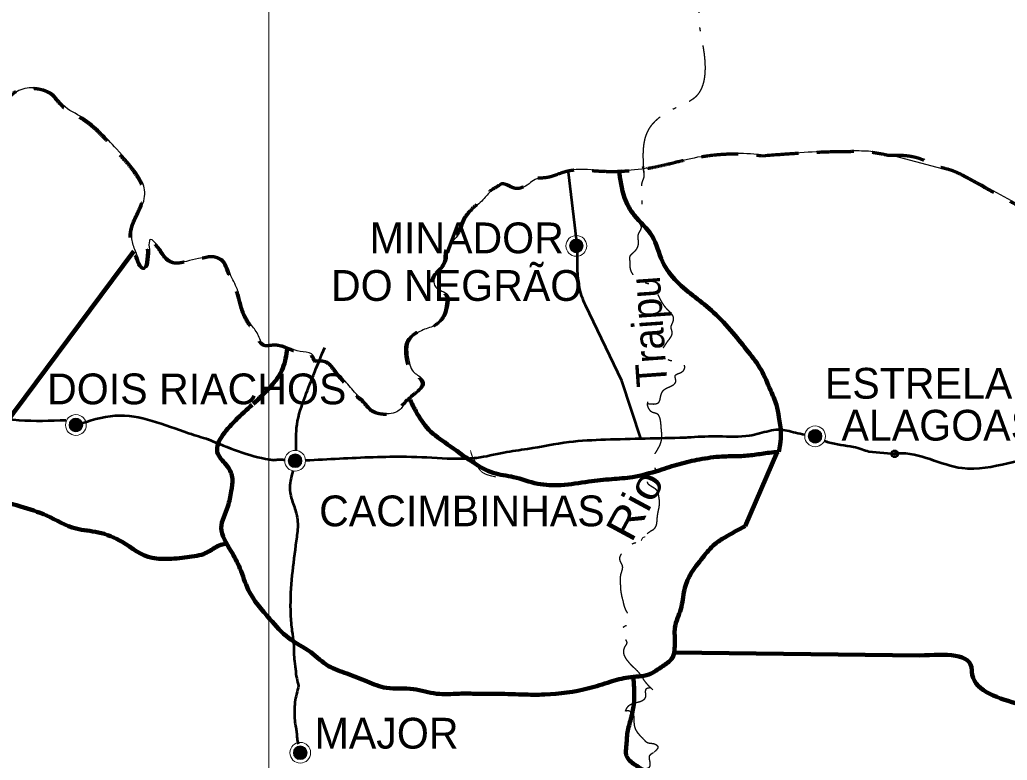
# Model space of a CAD drawing. Extents: x 512883 to 1063249, y 8784064 to 9081064.
# Drawn here: x 707317 to 755485, y 8945263 to 8981350 of the extents above; entities that cross this region are included whole.
import ezdxf

# ---------------------------------------------------------------- set-up
doc = ezdxf.new("R2010")
doc.units = 0
doc.header["$LTSCALE"] = 600
doc.header["$PDMODE"] = 32
doc.header["$PDSIZE"] = 300
doc.linetypes.add('DOT_DASHED', pattern=[7.7, 5, -1.2, 0.3, -1.2])
doc.linetypes.add('MEDIUM_DASHED', pattern=[4.5, 3, -1.5])
for name, color, linetype, lineweight in [('1', 7, 'Continuous', 25), ('10', 7, 'Continuous', 53), ('13', 7, 'Continuous', 90), ('20', 7, 'Continuous', 53), ('4', 7, 'Continuous', 13), ('5', 7, 'Continuous', 13), ('7', 7, 'Continuous', 13)]:
    doc.layers.add(name, color=color, linetype=linetype, lineweight=lineweight)

msp = doc.modelspace()

# ---------------------------------------------------------------- linework, layer by layer
at = {"layer": '1', "lineweight": 13}
msp.add_line((719468, 8831691.5), (719468, 9039622), dxfattribs=at)
at = {"layer": '10'}
for p, q in [((734465.8, 8970661.9), (734079.7, 8973916.1)), ((736689.1, 8963752.3), (734911.5, 8967437.8)), ((737616.8, 8960937.3), (736689.1, 8963752.3)), ((748733, 8960303.9), (750009.2, 8960196.7))]:
    msp.add_line(p, q, dxfattribs=at)
for points in [[(734911.5, 8967437.8), (734735.5, 8967867), (734521.7, 8969592.1), (734526.8, 8969856.2), (734531.9, 8970037.6)], [(710095.1, 8961612.2), (711975.7, 8962060.5), (715550.1, 8961209.8), (716524.6, 8960901)], [(739750.2, 8960990), (740069.8, 8961013.6), (741413.6, 8961055), (742910, 8961091.3), (743877.1, 8961319.2), (744319.9, 8961381.4), (745159.8, 8961231.2), (745615.5, 8961134.3)], [(716504.4, 8960907.4), (719500.2, 8959922.9), (719710, 8959891.7)], [(728165.2, 8959972.1), (728754.8, 8959967.2), (729599.7, 8960008.6), (730928.2, 8960262.5), (732088.7, 8960443.8), (734109.4, 8960775.3), (735885.8, 8960894.5), (739750.2, 8960990)], [(746576.9, 8960831.1), (746747.9, 8960770.1), (747984.7, 8960537), (748391.9, 8960423.1), (748733, 8960303.9)], [(720248.7, 8959891.2), (720043.6, 8959901.7), (719817.2, 8959894.6), (719710, 8959891.7)], [(721260.6, 8959880.5), (724555.5, 8960039.7), (726184.3, 8960060.4), (728165.2, 8959972.1)], [(760025.4, 8958989.5), (758791.9, 8960070.6), (757224, 8960086.4), (755519.6, 8959726.1), (753291.3, 8959489.3), (750147.9, 8960209.6), (749997.5, 8960195.6)], [(720637.5, 8959358.1), (720493.7, 8958423.5), (720600.6, 8957921), (720809.3, 8957273.5), (720870.4, 8956512), (720773.7, 8955745.3), (720763.1, 8955633.6)], [(720771.7, 8955725), (720524.3, 8952373), (720595.5, 8951564.9), (720671.9, 8950969.1), (720702.4, 8950212.8), (720763.5, 8949710.3), (720824.6, 8949254.5), (720916.2, 8948886.7)], [(720916.2, 8948886.7), (720742.3, 8948088.2), (720732, 8947211.2), (720783.5, 8946853.1), (720819.6, 8946619.6), (720845.4, 8946323.8), (720896.9, 8946048.7)]]:
    msp.add_spline(points, degree=3, dxfattribs=at)
msp.add_point((749997.5, 8960195.6), dxfattribs=at)
at = {"layer": '13', "lineweight": 25}
for p, q in [((753350.1, 8973817.3), (749745.8, 8974773.5)), ((732684.5, 8973664.1), (732612.3, 8973629.6)), ((721878.7, 8964741.6), (721780.9, 8964695.6))]:
    msp.add_line(p, q, dxfattribs=at)
at = {"layer": '13'}
for p, q in [((712886.7, 8970072.6), (705949.8, 8960800.5)), ((742703.1, 8956675), (744263.7, 8960282.7)), ((739246.1, 8950519.4), (751215.9, 8950362.8))]:
    msp.add_line(p, q, dxfattribs=at)
at = {"layer": '13', "linetype": 'MEDIUM_DASHED', "lineweight": 70}
msp.add_lwpolyline([(721689.3, 8964678.9), (721746.9, 8964737.1), (721787.2, 8964724.9)], dxfattribs=at)
for points in [[(706159.5, 8976374.6), (706429.7, 8976990.8), (706677.5, 8977367.7), (706839.2, 8977612.2), (707097.1, 8977836.4), (707895.8, 8978014.7), (708826.1, 8977734.5), (709336.7, 8977179.2), (710297.3, 8976562.9), (711940.3, 8975044.9), (713017.2, 8973740.8), (713315.5, 8973043), (713300.3, 8972620.2), (712921.1, 8971662.5), (712744.2, 8971209.2), (712703.7, 8970582.6), (712895.8, 8969991.7), (713057.6, 8969558.7), (713234.6, 8969283.7), (713361, 8969242.9), (713527.8, 8969645.3), (713553.1, 8970159.8), (713553.1, 8970567.3), (713573.3, 8970608.1), (713816, 8970480.7), (714169.9, 8970047.8), (714382.2, 8969752.3), (714801.8, 8969518), (715363, 8969558.7), (715944.4, 8969696.3), (716348.8, 8969767.6), (716596.6, 8969818.5), (717142.6, 8969630.1), (717486.3, 8968957.7), (717840.2, 8968188.5), (718017.2, 8967602.7), (718194.1, 8967037.2), (718527.8, 8966451.5), (718871.6, 8965931.9), (719008.1, 8965636.4), (719164.8, 8965514.2), (719738.5, 8965507.8), (720910.6, 8965166.7), (721451.4, 8965051.3), (721689.3, 8964678.9)], [(732593, 8973647.4), (733055.8, 8973679.3), (734017.8, 8973979.7), (735473.6, 8973984.9), (738247.6, 8974166.2), (740120.7, 8974596.2), (742869.3, 8974793), (743500, 8974726.3)], [(743500, 8974726.3), (746671.5, 8974917.3), (747832, 8974938.1), (748738.1, 8974912.2), (749654.2, 8974756.8)], [(749654.2, 8974756.8), (751133.8, 8974617.1), (752173.2, 8974188.4), (752784.7, 8974014.9), (753246, 8973806.2)], [(753258.6, 8973800.6), (756145, 8972228.3), (758126.6, 8971149.5), (759060.8, 8970276.1), (759489.1, 8967898.4), (760156.5, 8967525), (761008.9, 8966776.5), (761311.1, 8966714.8), (761418.5, 8967904.7), (761819.8, 8967968.6), (761964.4, 8967614.3), (763228, 8966032.4), (763365, 8966366.7), (763825, 8966576.9), (764463.7, 8966975.4), (765249.4, 8966811), (765751.8, 8966812.7), (766047.5, 8967335.3), (766506.4, 8968208.9)], [(721787.2, 8964724.9), (722154.8, 8964707.5), (722726.1, 8964148.7), (723165.9, 8963646.2), (723691.6, 8963046.4), (724060.7, 8962718.2), (724460, 8962302.9), (724869.5, 8962159.4), (725238.6, 8962133.7), (725617.7, 8962226), (726001.9, 8962600.3), (726527.7, 8963087.4), (726891.6, 8963425.8), (726957.3, 8963579.6), (726856.2, 8963835.9), (726416.4, 8964189.7), (726254.7, 8964517.8), (726148.5, 8965138.2), (726214.2, 8965650.9), (726461.9, 8965958.6), (727053.4, 8966276.4), (727660, 8966527.7), (728034.1, 8966999.4), (728155.5, 8967542.8), (728145.3, 8967871), (727907.7, 8968070.9), (727569, 8968255.5), (727432.5, 8968465.7), (727493.2, 8968829.7), (727852.1, 8969245), (728059.4, 8969639.8), (728079.6, 8969952.6), (728180.7, 8970301.2), (728615.5, 8970865.2), (728797.5, 8971203.6), (728984.5, 8971654.8), (729358.6, 8972116.2), (729884.4, 8972628.9), (730283.7, 8973034), (730678, 8973274.9), (730804.4, 8973357), (731244.2, 8973223.7), (731704.3, 8973151.9), (732068.2, 8973336.5), (732361.5, 8973551.8), (732520.8, 8973612.9)]]:
    msp.add_spline(points, degree=3, dxfattribs=at)
at = {"layer": '13', "lineweight": 25}
for points in [[(721780.9, 8964695.6), (721542.9, 8965068), (721002.1, 8965183.4), (719830.1, 8965524.5), (719256.3, 8965530.9), (719099.6, 8965653.1), (718963.1, 8965948.6), (718619.3, 8966468.2), (718285.7, 8967054), (718108.7, 8967619.4), (717931.8, 8968205.2), (717577.9, 8968974.4), (717234.1, 8969646.8), (716688.1, 8969835.2), (716440.4, 8969784.3), (716035.9, 8969713), (715454.5, 8969575.5), (714893.4, 8969534.7), (714473.7, 8969769), (714261.4, 8970064.5), (713907.5, 8970497.5), (713664.8, 8970624.8), (713644.6, 8970584.1), (713644.6, 8970176.5), (713619.3, 8969662.1), (713452.5, 8969259.6), (713326.1, 8969300.4), (713149.2, 8969575.5), (712987.4, 8970008.4), (712795.3, 8970599.3), (712835.7, 8971225.9), (713012.7, 8971679.2), (713391.8, 8972636.9), (713407, 8973059.7), (713108.7, 8973757.6), (712031.9, 8975061.6), (710388.8, 8976579.6), (709428.2, 8977196), (708917.6, 8977751.2), (707987.4, 8978031.4), (707188.6, 8977853.1), (706930.8, 8977628.9), (706769, 8977384.4), (706521.3, 8977007.5), (706251, 8976391.3)], [(743591.5, 8974743), (742960.8, 8974809.7), (740212.2, 8974612.9), (738339.1, 8974182.9), (735565.1, 8974001.6), (734109.3, 8973996.4), (733147.3, 8973696), (732684.5, 8973664.1)], [(749745.8, 8974773.5), (748829.6, 8974928.9), (747923.6, 8974954.8), (746763.1, 8974934), (743591.5, 8974743)], [(766531.3, 8968098.7), (766139.1, 8967352), (765843.4, 8966829.4), (765340.9, 8966827.7), (764555.2, 8966992.2), (763916.5, 8966593.6), (763456.6, 8966383.4), (763319.6, 8966049.1), (762055.9, 8967631), (761911.3, 8967985.3), (761510.1, 8967921.4), (761402.6, 8966731.5), (761100.5, 8966793.2), (760248, 8967541.7), (759580.7, 8967915.2), (759152.4, 8970292.8), (758218.2, 8971166.2), (756236.6, 8972245), (753350.1, 8973817.3)], [(732612.3, 8973629.6), (732453, 8973568.5), (732159.8, 8973353.2), (731795.8, 8973168.6), (731335.8, 8973240.4), (730896, 8973373.7), (730769.6, 8973291.7), (730375.3, 8973050.7), (729975.9, 8972645.6), (729450.2, 8972132.9), (729076.1, 8971671.5), (728889, 8971220.3), (728707, 8970881.9), (728272.3, 8970317.9), (728171.2, 8969969.3), (728150.9, 8969656.5), (727943.7, 8969261.7), (727584.8, 8968846.5), (727524.1, 8968482.4), (727660.6, 8968272.2), (727999.3, 8968087.6), (728236.9, 8967887.7), (728247, 8967559.5), (728125.7, 8967016.1), (727751.6, 8966544.4), (727144.9, 8966293.2), (726553.5, 8965975.3), (726305.8, 8965667.6), (726240, 8965154.9), (726346.2, 8964534.6), (726508, 8964206.4), (726947.8, 8963852.6), (727048.9, 8963596.3), (726983.2, 8963442.5), (726619.2, 8963104.1), (726093.4, 8962617), (725709.2, 8962242.7), (725330.1, 8962150.4), (724961.1, 8962176.1), (724551.6, 8962319.6), (724152.2, 8962734.9), (723783.2, 8963063.1), (723257.4, 8963662.9), (722817.6, 8964165.4), (722246.4, 8964724.2), (721878.7, 8964741.6)]]:
    msp.add_spline(points, degree=3, dxfattribs=at)
at = {"layer": '13'}
for points in [[(736550.5, 8974034.8), (736820.9, 8972666.4), (737287.4, 8971829), (738159.6, 8970807.9), (738666.7, 8969562.1), (739376.6, 8968581.7), (741161.5, 8967090.8), (742094.6, 8966090.1), (742865.3, 8965150.7), (743473.8, 8964292.9), (743940.3, 8963292.1), (744224.3, 8962577.3), (744346, 8961985.1), (744447.4, 8961209), (744406.9, 8960657.6), (744346, 8960289.9)], [(720360, 8965327.6), (720148.1, 8964374.6), (719559.9, 8963476), (718702.8, 8962631.9)], [(726317.6, 8962899.8), (726638.7, 8962271), (727267.5, 8961372.4), (728180.3, 8960657.6), (729397.3, 8959799.8), (730411.4, 8959268.8), (731405.3, 8959064.6), (732581.7, 8958737.8), (733717.6, 8958676.5), (735076.6, 8958839.9), (736192.2, 8958962.4), (737206.3, 8959064.6), (738504.4, 8959391.3), (739498.3, 8959697.7), (740471.9, 8959922.3), (741567.2, 8960065.3), (742439.4, 8960085.7), (743149.3, 8960147), (743879.5, 8960249.1), (744346, 8960289.9)], [(718651.7, 8962582.6), (717835.8, 8961821.7), (716983.9, 8960187.8), (717450.4, 8959575.1), (717693.8, 8958982.8), (717633, 8958370.2), (717470.7, 8957634.9), (717146.2, 8956593.3), (717612.7, 8955470.1), (718058.9, 8954612.3), (718464.6, 8953570.7), (719519.3, 8952141.1), (720432.1, 8951222.1), (721507.1, 8950527.7), (722379.3, 8949853.7), (723271.7, 8949486.1), (724265.6, 8949098), (725198.6, 8948791.7), (726517, 8948730.4), (727652.9, 8948505.8), (728748.2, 8948505.8), (729519, 8948505.8), (730452, 8948505.8), (731831.2, 8948464.9), (732926.6, 8948464.9), (735076.6, 8948771.3), (736111, 8949077.6), (737003.5, 8949302.3), (737997.4, 8949445.2), (738687, 8949853.7), (739112.9, 8950200.9), (739275.2, 8950588.9)], [(703678.1, 8958901.2), (704347.5, 8958513.1), (705807.8, 8958043.4), (707349.4, 8957634.9), (708627.2, 8957185.6), (710067.3, 8956552.5), (711142.3, 8956368.7), (712318.8, 8955899), (713779.2, 8955122.9), (714205.1, 8955082), (715239.6, 8955122.9), (716187.9, 8955271)], [(739237.1, 8950497.7), (739275.2, 8950936.1), (739275.2, 8951732.6), (739559.2, 8952631.2), (739741.7, 8953570.7), (740025.7, 8954306), (740634.2, 8955143.3), (741222.4, 8955796.8), (741709.2, 8956123.6), (742703.1, 8956675)], [(716187.9, 8955271), (716524, 8955430.5), (717125.9, 8955756), (717430.1, 8955819.6)], [(751215.9, 8950362.8), (753762, 8949641), (753762.7, 8949578.4), (755890.1, 8948041), (757527.9, 8947149), (757853, 8946837), (757993.7, 8946837.5), (759997, 8947428.2), (761876.7, 8948289.9), (763609.1, 8949756.3), (764914.3, 8949864.8), (765859.8, 8949784.4), (767129, 8949517.2), (767844.7, 8948413.5), (770470.8, 8945520.4)], [(737243.3, 8949342.3), (737287.4, 8948648.7), (737267.2, 8947974.8), (737125.2, 8947280.4), (736962.9, 8946626.8), (736902.1, 8945932.4), (736902.1, 8945524), (737246.9, 8945095.1), (737875.7, 8944645.8), (738058.2, 8944359.9)]]:
    msp.add_spline(points, degree=3, dxfattribs=at)
at = {"layer": '20'}
for points in [[(720798.7, 8960361.7), (720842.3, 8961626.5), (721234.4, 8962978.6), (722193, 8965377.4)], [(709566.7, 8961827.1), (707282.2, 8961827.1), (704947, 8962237.3), (703424, 8962724.3), (701647.2, 8963211.3), (700048.1, 8962673), (698753.5, 8961673.3), (697357.5, 8961827.1), (696189.8, 8962468), (695352.2, 8963493.3), (694574.4, 8963871.8), (693066.1, 8963771.4)]]:
    msp.add_spline(points, degree=3, dxfattribs=at)
at = {"layer": '4', "linetype": 'DOT_DASHED', "lineweight": 25}
for points in [[(737771.9, 8973878.1), (738007.4, 8976016.7), (739042.5, 8976929.5), (740383.3, 8977697.2), (740702.9, 8979750.7), (740453.3, 8981596.7), (740956.7, 8983442.9), (741968, 8985558.7), (742250.1, 8986512.9), (742185.8, 8987633), (742689.7, 8989292.4), (743519, 8990993.4)], [(737946.5, 8962644.2), (738502.1, 8962723.1), (738588.6, 8963033.9), (738731.1, 8963303.3), (739097.6, 8963500.1), (739316.5, 8963722.9), (739291, 8964002.6), (739591.3, 8964173.5), (739749.1, 8964370.4), (739642.2, 8964665.7), (739464.1, 8964727.8), (739087.4, 8964727.8), (738878.8, 8964815.9), (738649.7, 8965142.2), (738782, 8965468.6), (738960.2, 8965727.6), (739143.4, 8966121.3), (739087.4, 8966370), (739153.6, 8966556.4), (739209.6, 8966820.6), (738899.1, 8967235.1), (738593.7, 8967675.4), (738344.3, 8968162.3), (738217.1, 8968359.2), (737967.6, 8968483.5), (737484.1, 8968680.3), (737285.6, 8968866.8), (737112.5, 8969188), (737087.1, 8969576.5), (737087.1, 8969814.8), (737336.5, 8970089.4), (737499.4, 8970462.3), (737499.4, 8970907.8), (737641.9, 8971239.4), (737484.1, 8971591.6), (737509.5, 8971778.1), (737667.3, 8972249.5), (737667.3, 8972570.7), (737611.3, 8972891.9), (737626.6, 8972995.5), (737687.7, 8973446.2), (737779.3, 8973746.6), (737753.9, 8973974.5), (737708.1, 8974155.8), (737692.8, 8974186.9)], [(738201.8, 8948689.8), (737830.2, 8949083.5), (737535, 8949513.5), (737250, 8949798.4), (737005.6, 8950062.6), (736837.7, 8950316.4), (736776.6, 8950518.5), (736847.8, 8950803.4), (736939.5, 8951000.2), (736837.7, 8951176.3), (736685, 8951378.4), (736679.9, 8951632.2), (736817.3, 8951792.8), (737051.5, 8951927.5), (737076.9, 8952207.2), (736903.8, 8952538.7), (736751.1, 8953010.1), (736649.3, 8953491.9), (736623.9, 8953968.5), (736639.2, 8954305.2), (736720.6, 8954724.8), (736608.6, 8954978.6), (736588.3, 8955113.3), (736766.4, 8955439.7), (736970, 8955672.8), (737367, 8955869.6), (737575.7, 8955931.8), (737708.1, 8956040.6), (738003.3, 8956372.1), (738303.6, 8956584.5), (738400.3, 8956879.8), (738415.6, 8957092.2), (738456.3, 8957361.5), (738522.5, 8957744.9), (738491.9, 8958123), (738415.6, 8958382), (738059.3, 8958651.4), (737947.3, 8958786.1), (738013.5, 8958967.4), (738278.1, 8959102.1), (738334.1, 8959412.9), (738196.7, 8959832.5), (738354.5, 8960283.2), (738558.1, 8960656.2), (738634.4, 8960982.5), (738609, 8961443.6), (738563.2, 8961858), (738430.8, 8962127.3), (738130.5, 8962241.3), (738023.6, 8962370.8), (737942.2, 8962578), (737956, 8962722.8)], [(736860.6, 8947657.4), (737015.5, 8947911.8), (737309.3, 8948057.1), (737613.4, 8948140.1), (737840.2, 8948316.6), (737845.4, 8948586.4), (737881.4, 8948742.1), (738092.3, 8948805.9)], [(736860.6, 8947657.4), (736943.3, 8947683.4), (737226.8, 8947512.2), (737273.2, 8947216.4), (737340.2, 8946796), (737613.4, 8946422.4), (737778.3, 8946251.1), (737891.8, 8946147.3), (738097.9, 8946090.2), (738278.3, 8946059.1), (738438.1, 8945934.5), (738255.1, 8945651.8)], [(737337.2, 8944270.8), (737386.6, 8944419.2), (737536.1, 8944445.1), (737618.6, 8944434.7), (737665, 8944766.9), (737788.7, 8944849.9), (737938.1, 8944875.8), (738030.9, 8944932.9), (738051.6, 8945233.9), (738041.2, 8945472.7), (738175.3, 8945607.6), (738230.5, 8945639.6)]]:
    msp.add_spline(points, degree=3, dxfattribs=at)
at = {"layer": '4', "linetype": 'DOT_DASHED'}
for points in [[(730546.5, 8959071), (729772.8, 8959392.2), (729533.5, 8959817), (729401.2, 8960050.1), (729304.5, 8960355.7)], [(737632.9, 8955970.8), (737753.9, 8956133.8), (737818.1, 8956144.6)]]:
    msp.add_spline(points, degree=3, dxfattribs=at)
at = {"layer": '5'}
for p, q in [((734148.3, 8970428), (734783.1, 8970428)), ((734159.1, 8970458), (734772.3, 8970458.3)), ((734173.5, 8970488), (734758.2, 8970488)), ((734191.8, 8970518), (734739.9, 8970518)), ((734215.8, 8970548), (734716.2, 8970548)), ((734244.9, 8970578), (734686.5, 8970578)), ((734284.5, 8970608), (734646.9, 8970608)), ((734341.8, 8970638), (734589.6, 8970638)), ((734133.3, 8970338), (734798.1, 8970338)), ((734133.9, 8970308), (734797.8, 8970308)), ((734135.4, 8970368), (734796, 8970368)), ((734136.9, 8970278), (734794.5, 8970278)), ((734140.2, 8970398), (734791.2, 8970398)), ((734142.9, 8970248), (734788.5, 8970248)), ((734151.9, 8970218), (734779.5, 8970218)), ((734164.5, 8970188), (734767.2, 8970188.3)), ((734180.4, 8970158), (734751, 8970158)), ((734201.1, 8970128), (734730.6, 8970128.3)), ((734226.3, 8970097.7), (734705.4, 8970098)), ((734259.6, 8970068), (734671.8, 8970068)), ((734304.6, 8970038), (734626.8, 8970038)), ((734378.4, 8970008), (734552.7, 8970008)), ((709763.8, 8961759.8), (710348.5, 8961759.8)), ((709782.1, 8961789.8), (710330.2, 8961789.8)), ((709806.1, 8961819.8), (710306.5, 8961819.8)), ((709835.2, 8961849.8), (710276.8, 8961849.8)), ((709874.8, 8961879.8), (710237.2, 8961879.8)), ((709932.1, 8961909.8), (710179.9, 8961909.8)), ((709723.6, 8961609.8), (710388.4, 8961609.8)), ((709724.2, 8961579.8), (710388.1, 8961579.8)), ((709725.7, 8961639.8), (710386.3, 8961639.8)), ((709727.2, 8961549.8), (710384.8, 8961549.8)), ((709730.5, 8961669.8), (710381.5, 8961669.8)), ((709733.2, 8961519.8), (710378.8, 8961519.8)), ((709738.6, 8961699.8), (710373.4, 8961699.8)), ((709742.2, 8961489.8), (710369.8, 8961489.8)), ((709749.4, 8961729.8), (710362.6, 8961730.1)), ((709754.8, 8961459.8), (710357.5, 8961460.1)), ((709770.7, 8961429.8), (710341.3, 8961429.8)), ((709791.4, 8961399.8), (710320.9, 8961400.1)), ((709816.6, 8961369.5), (710295.7, 8961369.8)), ((709849.9, 8961339.8), (710262.1, 8961339.8)), ((709894.9, 8961309.8), (710217.1, 8961309.8)), ((709968.7, 8961279.8), (710143, 8961279.8)), ((745861.6, 8961269.1), (746362, 8961269.1)), ((745890.7, 8961299.1), (746332.3, 8961299.1)), ((745930.3, 8961329.1), (746292.7, 8961329.1)), ((745987.6, 8961359.1), (746235.4, 8961359.1)), ((745779.1, 8961059.1), (746443.9, 8961059.1)), ((745779.7, 8961029.1), (746443.6, 8961029.1)), ((745781.2, 8961089.1), (746441.8, 8961089.1)), ((745782.7, 8960999.1), (746440.3, 8960999.1)), ((745786, 8961119.1), (746437, 8961119.1)), ((745788.7, 8960969.1), (746434.3, 8960969.1)), ((745794.1, 8961149.1), (746428.9, 8961149.1)), ((745797.7, 8960939.1), (746425.3, 8960939.1)), ((745804.9, 8961179.1), (746418.1, 8961179.4)), ((745810.3, 8960909.1), (746413, 8960909.4)), ((745819.3, 8961209.1), (746404, 8961209.1)), ((745826.2, 8960879.1), (746396.8, 8960879.1)), ((745837.6, 8961239.1), (746385.7, 8961239.1)), ((745846.9, 8960849.1), (746376.4, 8960849.4)), ((745872.1, 8960818.8), (746351.2, 8960819.1)), ((745905.4, 8960789.1), (746317.6, 8960789.1)), ((745950.4, 8960759.1), (746272.6, 8960759.1)), ((746024.2, 8960729.1), (746198.5, 8960729.1)), ((720415.8, 8959868.8), (721080.6, 8959868.8)), ((720416.4, 8959838.8), (721080.3, 8959838.8)), ((720417.9, 8959898.8), (721078.5, 8959898.8)), ((720422.7, 8959928.8), (721073.7, 8959928.8)), ((720430.8, 8959958.8), (721065.6, 8959958.8)), ((720441.6, 8959988.8), (721054.8, 8959989.1)), ((720456, 8960018.8), (721040.7, 8960018.8)), ((720474.3, 8960048.8), (721022.4, 8960048.8)), ((720498.3, 8960078.8), (720998.7, 8960078.8)), ((720527.4, 8960108.8), (720969, 8960108.8)), ((720567, 8960138.8), (720929.4, 8960138.8)), ((720624.3, 8960168.8), (720872.1, 8960168.8)), ((720419.4, 8959808.8), (721077, 8959808.8)), ((720425.4, 8959778.8), (721071, 8959778.8)), ((720434.4, 8959748.8), (721062, 8959748.8)), ((720447, 8959718.8), (721049.7, 8959719.1)), ((720462.9, 8959688.8), (721033.5, 8959688.8)), ((720483.6, 8959658.8), (721013.1, 8959659.1)), ((720508.8, 8959628.5), (720987.9, 8959628.8)), ((720542.1, 8959598.8), (720954.3, 8959598.8)), ((720587.1, 8959568.8), (720909.3, 8959568.8)), ((720660.9, 8959538.8), (720835.2, 8959538.8)), ((720779.2, 8945876.9), (721220.8, 8945876.9)), ((720818.8, 8945906.9), (721181.2, 8945906.9)), ((720876.1, 8945936.9), (721123.9, 8945936.9)), ((720667.6, 8945636.9), (721332.4, 8945636.9)), ((720668.2, 8945606.9), (721332.1, 8945606.9)), ((720669.7, 8945666.9), (721330.3, 8945666.9)), ((720671.2, 8945576.9), (721328.8, 8945576.9)), ((720674.5, 8945696.9), (721325.5, 8945696.9)), ((720677.2, 8945546.9), (721322.8, 8945546.9)), ((720682.6, 8945726.9), (721317.4, 8945726.9)), ((720686.2, 8945516.9), (721313.8, 8945516.9)), ((720693.4, 8945756.9), (721306.6, 8945757.2)), ((720698.8, 8945486.9), (721301.5, 8945487.2)), ((720707.8, 8945786.9), (721292.5, 8945786.9)), ((720714.7, 8945456.9), (721285.3, 8945456.9)), ((720726.1, 8945816.9), (721274.2, 8945816.9)), ((720735.4, 8945426.9), (721264.9, 8945427.2)), ((720750.1, 8945846.9), (721250.5, 8945846.9)), ((720760.6, 8945396.7), (721239.7, 8945396.9)), ((720793.9, 8945366.9), (721206.1, 8945366.9)), ((720838.9, 8945336.9), (721161.1, 8945336.9)), ((720912.7, 8945306.9), (721087, 8945306.9))]:
    msp.add_line(p, q, dxfattribs=at)
for centre, radius in [((734465.8, 8970329), 506.1), ((734465.8, 8970329), 332.9), ((710056.1, 8961600.8), 506.1), ((710056.1, 8961600.8), 332.9), ((746111.5, 8961050.1), 506.1), ((746111.5, 8961050.1), 332.9), ((720748.3, 8959859.8), 506.1), ((720748.3, 8959859.8), 332.9), ((721000.1, 8945627.9), 506.1), ((721000.1, 8945627.9), 332.9)]:
    msp.add_circle(centre, radius, dxfattribs=at)

# ---------------------------------------------------------------- texts
for s, p in [('MINADOR', (724385.3, 8969970.9)), ('DO NEGRÃO', (722496.9, 8967650.9)), ('ESTRELA DE', (746590.3, 8962884.2)), ('DOIS RIACHOS', (708649.7, 8962610.5)), ('ALAGOAS', (747400.9, 8960840.2)), ('CACIMBINHAS', (721919.6, 8956665)), ('MAJOR', (721699.9, 8945830.3))]:
    msp.add_text(s, height=1500, dxfattribs=at).set_placement(p)
at = {"layer": '7'}
for s, rotation, width, p in [('Traipu', 94.02, 0.95, (738911, 8963509.6)), ('Rio', 61.676, 1.15, (737156.9, 8955818.6))]:
    msp.add_text(s, height=1500, rotation=rotation, dxfattribs=dict(at, width=width)).set_placement(p)

doc.saveas('drawing.dxf')
